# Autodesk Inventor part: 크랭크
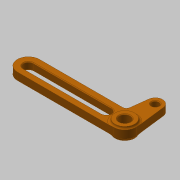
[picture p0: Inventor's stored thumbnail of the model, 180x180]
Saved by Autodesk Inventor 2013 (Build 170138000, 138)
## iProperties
Created: 2019-09
Part Number: 크랭크
Material: 알루미늄 6061
Document SubType Name: Modeling
Designer: mduedu
Density: 2.71 g/cm^3
Mass: 23.0159 g
Surface Area: 54.7148 cm^2
Volume: 8.49294 cm^3
Author: mduedu
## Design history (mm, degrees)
sketch "스케치1"
  geometry: L1 (0, 0)-(79, 0); L2 (0, 9)-(79, 9); L3 (10.637, -9)-(79, -9); L4 (0, 0)-(0, -25); L5 (-8.935, -1.08)-(-5.957, -25.72); L6 (7.659, -11.64)-(5.957, -25.72); L7 (79, -4)-(15, -4); L8 (15, 4)-(79, 4); C1 r 3 at (0, -25); A1 r 9 centre (0, 0) between (0, 9) and (-8.935, -1.08); A2 r 9 centre (79, 0) between (79, -9) and (79, 9); A3 r 6 centre (0, -25) between (-5.957, -25.72) and (5.957, -25.72); A4 r 3 centre (10.637, -12) between (10.637, -9) and (7.659, -11.64); A5 r 4 centre (79, 0) between (79, -4) and (79, 4); A6 r 4 centre (15, 0) between (15, -4) and (15, 4); 1 further point
  constraints: 16 end point, 13 point on circle, 12 tangent, 7 centre point, 5 coincident, 3 horizontal, 2 point on line, 1 equal radius, 1 perpendicular, 1 other
  dimensions: "d0" = 79 distance of L1.start L1.end; "d2" = 25 distance of L1.start L4.end; "d3" = 3 radius of A4; "d4" = 9 radius of A1; "d5" = 6 radius of A3; "d6" = 8 diameter of A5; "d7" = 64 distance of A6.centre L1.end; "d8" = 6 diameter of C1
extrude "돌출1" new body sketch "스케치1" stored distance "d9" = 6; taper "d10" = 0 deg
sketch "스케치2"
  geometry: C1 r 8 at (0, 0); 1 further point
  constraints: 1 centre point, 1 coincident
  dimensions: "d11" = 16 diameter of C1
extrude "돌출2" join sketch "스케치2" stored distance "d12" = 10; taper "d13" = 0 deg
sketch "스케치3"
  geometry: C1 r 4.5 at (0, 0); 1 further point
  constraints: 1 centre point, 1 coincident
  dimensions: "d14" = 9 diameter of C1
extrude "돌출3" cut sketch "스케치3" stored distance "d15" = 10; taper "d16" = 0 deg
fillet "모깎기1" dims "d17" = 2
chamfer "모따기1" distance "d18" = 0.5; stored, may be unused: second distance "d19" = 2, angle "d20" = 45 deg
node "솔리드1"
